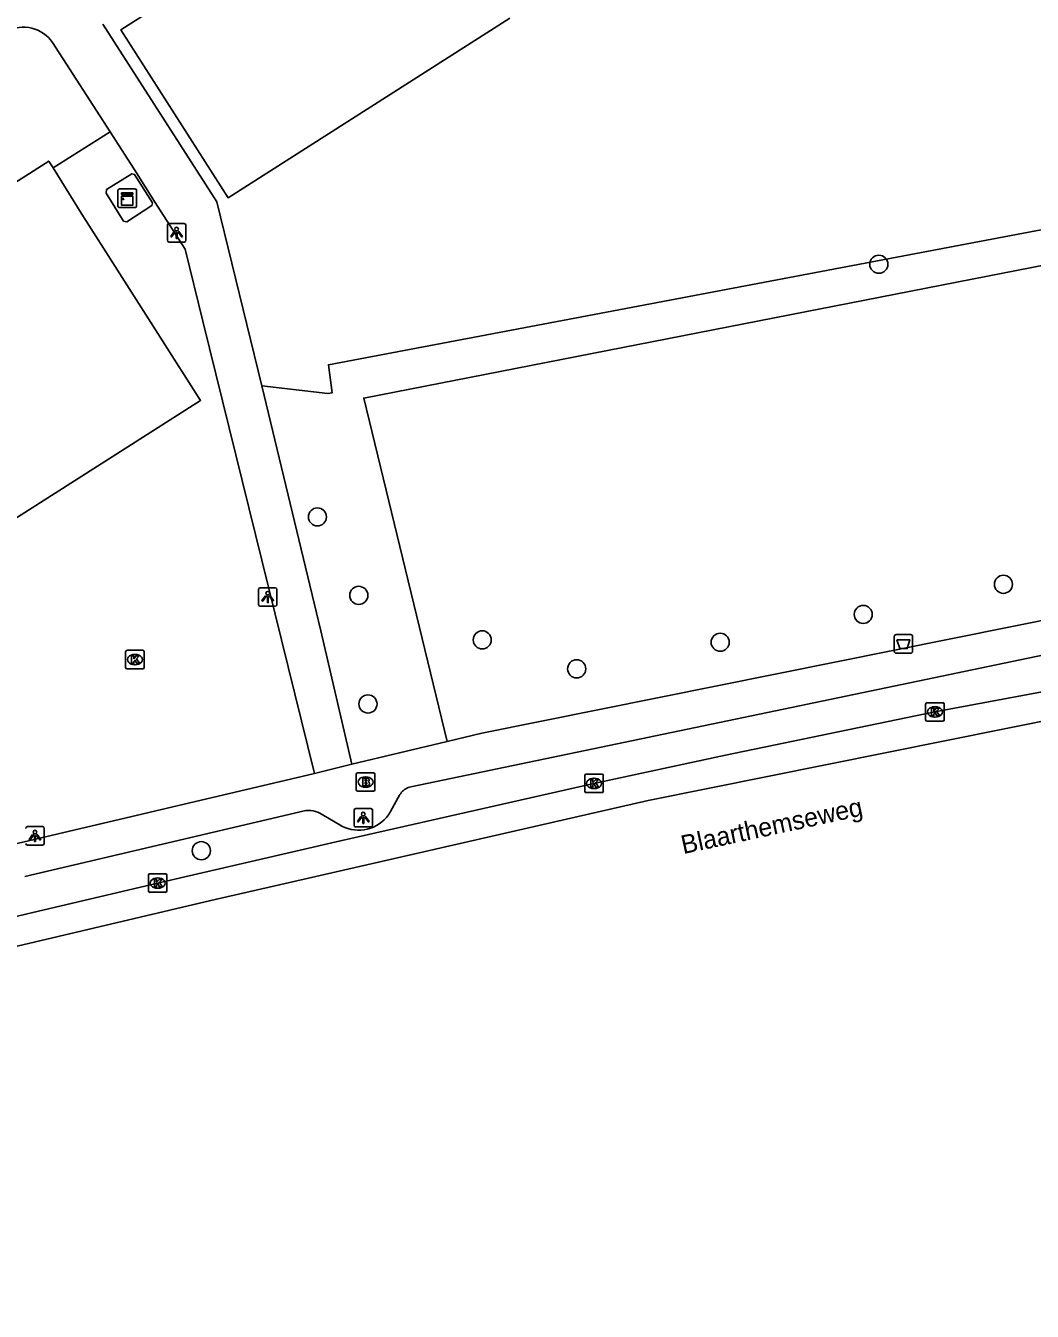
# Model space of a CAD drawing. Extents: x 159222 to 160346, y 381249 to 382166.
# Drawn here: x 159311.7 to 159366, y 381259.1 to 381328.4 of the extents above; entities that cross this region are included whole.
import ezdxf

# ---------------------------------------------------------------- set-up
doc = ezdxf.new("R2010")
doc.units = 0
for name, color, linetype in [('IMGEO_Afvalbak', 7, 'Continuous'), ('IMGEO_Boom', 7, 'Continuous'), ('IMGEO_Brandkraan', 7, 'Continuous'), ('IMGEO_Groenvoorziening', 7, 'Continuous'), ('IMGEO_Kast', 7, 'Continuous'), ('IMGEO_Kolk', 7, 'Continuous'), ('IMGEO_Lage_trafo', 7, 'Continuous'), ('IMGEO_Lichtpunt', 7, 'Continuous'), ('IMGEO_Openbare_ruimte_label', 7, 'Continuous'), ('IMGEO_Pand', 7, 'Continuous'), ('IMGEO_Rijbaan_lokaal_gesloten', 7, 'Continuous'), ('IMGEO_Voetpad_open', 7, 'Continuous')]:
    doc.layers.add(name, color=color, linetype=linetype)

msp = doc.modelspace()

# ---------------------------------------------------------------- linework, layer by layer
at = {"layer": 'IMGEO_Afvalbak'}
for p, q in [((159358.543, 381294.719), (159358.543, 381295.519)), ((159358.543, 381295.519), (159358.543, 381294.719)), ((159358.643, 381295.619), (159359.433, 381295.619)), ((159359.433, 381295.619), (159358.643, 381295.619)), ((159359.533, 381295.519), (159359.533, 381294.719)), ((159359.533, 381294.719), (159359.533, 381295.519)), ((159359.433, 381294.619), (159358.643, 381294.619)), ((159358.643, 381294.619), (159359.433, 381294.619))]:
    msp.add_line(p, q, dxfattribs=at)
msp.add_lwpolyline([(159358.686, 381295.333), (159359.39, 381295.333), (159359.241, 381294.863), (159358.835, 381294.863), (159358.686, 381295.333)], dxfattribs=at)
for centre, start, end in [((159358.643, 381295.519), 90, 180), ((159358.643, 381295.519), 90, 180), ((159359.433, 381295.519), 0, 90), ((159359.433, 381295.519), 360, 90), ((159358.643, 381294.719), 180, 270), ((159358.643, 381294.719), 180, 270), ((159359.433, 381294.719), 270, 0), ((159359.433, 381294.719), 270, 0)]:
    msp.add_arc(centre, 0.1, start, end, dxfattribs=at)
at = {"layer": 'IMGEO_Boom'}
for centre in [(159357.711, 381315.586), (159327.457, 381301.964), (159364.425, 381298.332), (159329.686, 381297.734), (159356.87, 381296.707), (159336.339, 381295.335), (159349.163, 381295.208), (159341.43, 381293.773), (159330.181, 381291.881), (159321.202, 381283.969)]:
    msp.add_circle(centre, 0.489, dxfattribs=at)
at = {"layer": 'IMGEO_Brandkraan'}
for p, q in [((159329.551, 381287.246), (159329.551, 381288.098)), ((159329.626, 381288.172), (159330.478, 381288.172)), ((159330.039, 381287.952), (159330.064, 381287.952)), ((159330.552, 381288.098), (159330.552, 381287.246)), ((159330.478, 381287.172), (159329.626, 381287.172)), ((159330.062, 381287.392), (159330.037, 381287.392))]:
    msp.add_line(p, q, dxfattribs=at)
for points in [[(159329.551, 381287.246), (159329.551, 381288.098)], [(159329.626, 381288.172), (159330.478, 381288.172)], [(159329.899, 381287.872), (159329.899, 381287.472), (159330.112, 381287.472)], [(159330.13, 381287.872), (159329.899, 381287.872)], [(159330.078, 381287.791), (159330.024, 381287.791), (159330.024, 381287.715)], [(159330.024, 381287.715), (159330.077, 381287.715)], [(159330.086, 381287.639), (159330.024, 381287.639), (159330.024, 381287.558)], [(159330.552, 381288.098), (159330.552, 381287.246)], [(159330.478, 381287.172), (159329.626, 381287.172)], [(159330.024, 381287.558), (159330.086, 381287.558)]]:
    msp.add_lwpolyline(points, dxfattribs=at)
for centre, radius, start, end in [((159329.628, 381288.096), 0.0765, 91.55205, 178.44795), ((159329.628, 381288.096), 0.0765, 91.55205, 178.44795), ((159330.079, 381287.753), 0.0379, 267.82845, 90.93552), ((159330.087, 381287.598), 0.0404, 269.87594, 90.50774), ((159330.134, 381287.727), 0.145, 59.4692, 91.53667), ((159330.159, 381287.774), 0.0922, 285.51372, 58.15012), ((159330.164, 381287.582), 0.105, 301.31148, 78.98903), ((159330.476, 381288.096), 0.0765, 1.55205, 88.44795), ((159330.476, 381288.096), 0.0765, 1.55205, 88.44795), ((159329.628, 381287.248), 0.0765, 181.55205, 268.44795), ((159329.628, 381287.248), 0.0765, 181.55205, 268.44795), ((159330.118, 381287.723), 0.251, 268.66757, 293.53466), ((159330.476, 381287.248), 0.0765, 271.55205, 358.44795), ((159330.476, 381287.248), 0.0765, 271.55205, 358.44795)]:
    msp.add_arc(centre, radius, start, end, dxfattribs=at)
for centre, major_axis, ratio, start_param, end_param in [((159330.038, 381287.672), (-0.387, 0.002), 0.722429, 4.712389, 7.853982), ((159330.063, 381287.672), (-0.39, 0.002), 0.717154, 1.570796, 4.712389)]:
    msp.add_ellipse(centre, major_axis=major_axis, ratio=ratio, start_param=start_param, end_param=end_param, dxfattribs=at)
at = {"layer": 'IMGEO_Groenvoorziening'}
for points in [[(159313.214, 381320.775), (159316.297, 381322.722)], [(159324.458, 381309.034), (159328.024, 381308.61), (159328.245, 381308.652), (159328.048, 381310.17), (159378.79, 381319.78), (159378.532, 381321.824), (159380.334, 381321.967), (159384.584, 381317.936), (159390.105, 381316.337)], [(159383.175, 381299.592), (159383.004, 381300.361), (159379.086, 381317.977), (159329.956, 381308.37), (159334.442, 381289.856)]]:
    msp.add_lwpolyline(points, dxfattribs=at)
at = {"layer": 'IMGEO_Kast'}
for p, q in [((159316.71, 381318.72), (159316.71, 381319.561)), ((159316.71, 381319.561), (159316.71, 381318.72)), ((159316.785, 381319.645), (159317.626, 381319.645)), ((159317.626, 381319.645), (159316.785, 381319.645)), ((159317.71, 381319.57), (159317.71, 381318.729)), ((159317.71, 381318.729), (159317.71, 381319.57)), ((159317.635, 381318.645), (159316.794, 381318.645)), ((159316.794, 381318.645), (159317.635, 381318.645))]:
    msp.add_line(p, q, dxfattribs=at)
for points in [[(159316.905, 381319.435), (159317.505, 381319.435), (159317.505, 381319.35), (159316.905, 381319.35), (159316.905, 381319.435)], [(159316.905, 381319.26), (159317.505, 381319.26), (159317.505, 381318.771), (159316.905, 381318.771), (159316.905, 381319.26)]]:
    msp.add_lwpolyline(points, dxfattribs=at)
msp.add_circle((159316.989, 381319.109), 0.0377, dxfattribs=at)
for centre, start, end in [((159316.788, 381319.567), 92.4484, 184.28452), ((159316.788, 381319.567), 92.4484, 184.28452), ((159317.632, 381319.567), 2.4484, 94.28452), ((159317.632, 381319.567), 2.4484, 94.28452), ((159316.788, 381318.723), 182.4484, 274.28452), ((159316.788, 381318.723), 182.4484, 274.28452), ((159317.632, 381318.723), 272.4484, 4.28452), ((159317.632, 381318.723), 272.4484, 4.28452)]:
    msp.add_arc(centre, 0.0779, start, end, dxfattribs=at)
at = {"layer": 'IMGEO_Kolk'}
for p, q in [((159317.122, 381293.846), (159317.122, 381294.698)), ((159317.197, 381294.772), (159318.049, 381294.772)), ((159317.61, 381294.552), (159317.635, 381294.552)), ((159318.123, 381294.698), (159318.123, 381293.846)), ((159317.633, 381293.992), (159317.608, 381293.992)), ((159318.049, 381293.772), (159317.197, 381293.772)), ((159360.233, 381291.024), (159360.233, 381291.876)), ((159360.308, 381291.95), (159361.16, 381291.95)), ((159360.721, 381291.73), (159360.746, 381291.73)), ((159361.234, 381291.876), (159361.234, 381291.024)), ((159360.744, 381291.17), (159360.719, 381291.17)), ((159361.16, 381290.95), (159360.308, 381290.95)), ((159341.863, 381287.172), (159341.863, 381288.024)), ((159341.938, 381288.098), (159342.79, 381288.098)), ((159342.351, 381287.878), (159342.376, 381287.878)), ((159342.864, 381288.024), (159342.864, 381287.172)), ((159342.79, 381287.098), (159341.938, 381287.098)), ((159342.374, 381287.318), (159342.349, 381287.318)), ((159318.424, 381282.725), (159319.276, 381282.725)), ((159318.349, 381281.799), (159318.349, 381282.651)), ((159318.837, 381282.505), (159318.862, 381282.505)), ((159319.35, 381282.651), (159319.35, 381281.799)), ((159319.276, 381281.725), (159318.424, 381281.725)), ((159318.86, 381281.945), (159318.835, 381281.945))]:
    msp.add_line(p, q, dxfattribs=at)
for points in [[(159317.122, 381293.846), (159317.122, 381294.698)], [(159317.197, 381294.772), (159318.049, 381294.772)], [(159318.123, 381294.698), (159318.123, 381293.846)], [(159317.443, 381294.472), (159317.566, 381294.472), (159317.566, 381294.321), (159317.696, 381294.472), (159317.86, 381294.472), (159317.714, 381294.321), (159317.867, 381294.072), (159317.715, 381294.072), (159317.63, 381294.236), (159317.566, 381294.169), (159317.566, 381294.072), (159317.443, 381294.072), (159317.443, 381294.472)], [(159318.049, 381293.772), (159317.197, 381293.772)], [(159360.233, 381291.024), (159360.233, 381291.876)], [(159360.308, 381291.95), (159361.16, 381291.95)], [(159361.234, 381291.876), (159361.234, 381291.024)], [(159360.554, 381291.65), (159360.677, 381291.65), (159360.677, 381291.499), (159360.807, 381291.65), (159360.971, 381291.65), (159360.825, 381291.499), (159360.978, 381291.25), (159360.826, 381291.25), (159360.741, 381291.414), (159360.677, 381291.347), (159360.677, 381291.25), (159360.554, 381291.25), (159360.554, 381291.65)], [(159361.16, 381290.95), (159360.308, 381290.95)], [(159341.863, 381287.172), (159341.863, 381288.024)], [(159341.938, 381288.098), (159342.79, 381288.098)], [(159342.184, 381287.798), (159342.307, 381287.798), (159342.307, 381287.647), (159342.437, 381287.798), (159342.601, 381287.798), (159342.455, 381287.647), (159342.608, 381287.398), (159342.456, 381287.398), (159342.371, 381287.562), (159342.307, 381287.495), (159342.307, 381287.398), (159342.184, 381287.398), (159342.184, 381287.798)], [(159342.864, 381288.024), (159342.864, 381287.172)], [(159342.79, 381287.098), (159341.938, 381287.098)], [(159318.424, 381282.725), (159319.276, 381282.725)], [(159318.349, 381281.799), (159318.349, 381282.651)], [(159318.67, 381282.425), (159318.793, 381282.425), (159318.793, 381282.274), (159318.923, 381282.425), (159319.087, 381282.425), (159318.941, 381282.274), (159319.094, 381282.025), (159318.942, 381282.025), (159318.857, 381282.189), (159318.793, 381282.122), (159318.793, 381282.025), (159318.67, 381282.025), (159318.67, 381282.425)], [(159319.35, 381282.651), (159319.35, 381281.799)], [(159319.276, 381281.725), (159318.424, 381281.725)]]:
    msp.add_lwpolyline(points, dxfattribs=at)
for centre, start, end in [((159317.199, 381294.696), 91.55205, 178.44795), ((159317.199, 381294.696), 91.55205, 178.44795), ((159318.047, 381294.696), 1.55205, 88.44795), ((159318.047, 381294.696), 1.55205, 88.44795), ((159317.199, 381293.848), 181.55205, 268.44795), ((159317.199, 381293.848), 181.55205, 268.44795), ((159318.047, 381293.848), 271.55205, 358.44795), ((159318.047, 381293.848), 271.55205, 358.44795), ((159360.31, 381291.874), 91.55205, 178.44795), ((159360.31, 381291.874), 91.55205, 178.44795), ((159361.158, 381291.874), 1.55205, 88.44795), ((159361.158, 381291.874), 1.55205, 88.44795), ((159360.31, 381291.026), 181.55205, 268.44795), ((159360.31, 381291.026), 181.55205, 268.44795), ((159361.158, 381291.026), 271.55205, 358.44795), ((159361.158, 381291.026), 271.55205, 358.44795), ((159341.94, 381288.022), 91.55205, 178.44795), ((159341.94, 381288.022), 91.55205, 178.44795), ((159342.788, 381288.022), 1.55205, 88.44795), ((159342.788, 381288.022), 1.55205, 88.44795), ((159341.94, 381287.174), 181.55205, 268.44795), ((159341.94, 381287.174), 181.55205, 268.44795), ((159342.788, 381287.174), 271.55205, 358.44795), ((159342.788, 381287.174), 271.55205, 358.44795), ((159318.426, 381282.649), 91.55205, 178.44795), ((159318.426, 381282.649), 91.55205, 178.44795), ((159319.274, 381282.649), 1.55205, 88.44795), ((159319.274, 381282.649), 1.55205, 88.44795), ((159318.426, 381281.801), 181.55205, 268.44795), ((159318.426, 381281.801), 181.55205, 268.44795), ((159319.274, 381281.801), 271.55205, 358.44795), ((159319.274, 381281.801), 271.55205, 358.44795)]:
    msp.add_arc(centre, 0.0765, start, end, dxfattribs=at)
for centre, major_axis, ratio, start_param, end_param in [((159317.609, 381294.272), (-0.387, 0.002), 0.722429, 4.712389, 7.853982), ((159317.634, 381294.272), (-0.39, 0.002), 0.717154, 1.570796, 4.712389), ((159360.72, 381291.45), (-0.387, 0.002), 0.722429, 4.712389, 7.853982), ((159360.745, 381291.45), (-0.39, 0.002), 0.717154, 1.570796, 4.712389), ((159342.35, 381287.598), (-0.387, 0.002), 0.722429, 4.712389, 7.853982), ((159342.375, 381287.598), (-0.39, 0.002), 0.717154, 1.570796, 4.712389), ((159318.836, 381282.225), (-0.387, 0.002), 0.722429, 4.712389, 7.853982), ((159318.861, 381282.225), (-0.39, 0.002), 0.717154, 1.570796, 4.712389)]:
    msp.add_ellipse(centre, major_axis=major_axis, ratio=ratio, start_param=start_param, end_param=end_param, dxfattribs=at)
at = {"layer": 'IMGEO_Lage_trafo'}
msp.add_lwpolyline([(159316.069, 381319.421), (159316.09, 381319.607), (159317.447, 381320.455), (159317.602, 381320.433), (159318.571, 381318.893), (159318.531, 381318.748), (159317.18, 381317.876), (159317.011, 381317.912), (159316.069, 381319.421)], dxfattribs=at)
at = {"layer": 'IMGEO_Lichtpunt'}
for p, q in [((159319.371, 381317.686), (159319.371, 381316.879)), ((159319.371, 381317.686), (159319.371, 381316.879)), ((159320.273, 381317.781), (159319.465, 381317.781)), ((159320.273, 381317.781), (159319.465, 381317.781)), ((159320.367, 381316.879), (159320.367, 381317.686)), ((159320.367, 381316.879), (159320.367, 381317.686)), ((159319.465, 381316.785), (159320.273, 381316.785)), ((159319.465, 381316.785), (159320.273, 381316.785)), ((159324.282, 381298.05), (159324.282, 381297.243)), ((159324.282, 381298.05), (159324.282, 381297.243)), ((159325.184, 381298.145), (159324.376, 381298.145)), ((159325.184, 381298.145), (159324.376, 381298.145)), ((159325.278, 381297.243), (159325.278, 381298.05)), ((159325.278, 381297.243), (159325.278, 381298.05)), ((159324.376, 381297.149), (159325.184, 381297.149)), ((159324.376, 381297.149), (159325.184, 381297.149)), ((159330.332, 381286.243), (159329.524, 381286.243)), ((159330.332, 381286.243), (159329.524, 381286.243)), ((159329.43, 381286.148), (159329.43, 381285.341)), ((159329.43, 381286.148), (159329.43, 381285.341)), ((159330.426, 381285.341), (159330.426, 381286.148)), ((159330.426, 381285.341), (159330.426, 381286.148)), ((159312.64, 381285.267), (159311.832, 381285.267)), ((159312.64, 381285.267), (159311.832, 381285.267)), ((159312.734, 381284.365), (159312.734, 381285.172)), ((159312.734, 381284.365), (159312.734, 381285.172)), ((159329.524, 381285.247), (159330.332, 381285.247)), ((159329.524, 381285.247), (159330.332, 381285.247)), ((159311.832, 381284.271), (159312.64, 381284.271)), ((159311.832, 381284.271), (159312.64, 381284.271))]:
    msp.add_line(p, q, dxfattribs=at)
for points in [[(159319.745, 381317.35), (159319.784, 381317.322), (159319.596, 381317.06), (159319.558, 381317.087), (159319.745, 381317.35)], [(159319.847, 381317.302), (159319.894, 381317.302), (159319.894, 381316.98), (159319.847, 381316.98), (159319.847, 381317.302)], [(159319.957, 381317.322), (159319.995, 381317.349), (159320.182, 381317.087), (159320.143, 381317.059), (159319.957, 381317.322)], [(159324.656, 381297.714), (159324.695, 381297.686), (159324.507, 381297.424), (159324.469, 381297.451), (159324.656, 381297.714)], [(159324.758, 381297.666), (159324.805, 381297.666), (159324.805, 381297.344), (159324.758, 381297.344), (159324.758, 381297.666)], [(159324.868, 381297.686), (159324.906, 381297.713), (159325.093, 381297.451), (159325.054, 381297.423), (159324.868, 381297.686)], [(159329.804, 381285.812), (159329.843, 381285.784), (159329.655, 381285.522), (159329.617, 381285.549), (159329.804, 381285.812)], [(159329.906, 381285.764), (159329.953, 381285.764), (159329.953, 381285.442), (159329.906, 381285.442), (159329.906, 381285.764)], [(159330.016, 381285.784), (159330.054, 381285.811), (159330.241, 381285.549), (159330.202, 381285.521), (159330.016, 381285.784)], [(159312.112, 381284.836), (159312.151, 381284.808), (159311.963, 381284.546), (159311.925, 381284.573), (159312.112, 381284.836)], [(159312.324, 381284.808), (159312.362, 381284.835), (159312.549, 381284.573), (159312.51, 381284.545), (159312.324, 381284.808)], [(159312.214, 381284.788), (159312.261, 381284.788), (159312.261, 381284.466), (159312.214, 381284.466), (159312.214, 381284.788)]]:
    msp.add_lwpolyline(points, dxfattribs=at)
for centre in [(159319.87, 381317.484), (159324.781, 381297.848), (159329.929, 381285.946), (159312.237, 381284.97)]:
    msp.add_circle(centre, 0.0994, dxfattribs=at)
for centre, start, end in [((159319.465, 381317.686), 90, 180), ((159319.465, 381317.686), 90, 180), ((159320.273, 381317.686), 0, 90), ((159320.273, 381317.686), 0, 90), ((159319.465, 381316.879), 180, 270), ((159319.465, 381316.879), 180, 270), ((159320.273, 381316.879), 270, 0), ((159320.273, 381316.879), 270, 360), ((159324.376, 381298.05), 90, 180), ((159324.376, 381298.05), 90, 180), ((159325.184, 381298.05), 0, 90), ((159325.184, 381298.05), 0, 90), ((159324.376, 381297.243), 180, 270), ((159324.376, 381297.243), 180, 270), ((159325.184, 381297.243), 270, 0), ((159325.184, 381297.243), 270, 360), ((159329.524, 381286.148), 90, 180), ((159329.524, 381286.148), 90, 180), ((159330.332, 381286.148), 0, 90), ((159330.332, 381286.148), 0, 90), ((159311.832, 381285.172), 90, 180), ((159311.832, 381285.172), 90, 180), ((159312.64, 381285.172), 0, 90), ((159312.64, 381285.172), 0, 90), ((159329.524, 381285.341), 180, 270), ((159329.524, 381285.341), 180, 270), ((159330.332, 381285.341), 270, 0), ((159330.332, 381285.341), 270, 360), ((159311.832, 381284.365), 180, 270), ((159311.832, 381284.365), 180, 270), ((159312.64, 381284.365), 270, 0), ((159312.64, 381284.365), 270, 360)]:
    msp.add_arc(centre, 0.0946, start, end, dxfattribs=at)
at = {"layer": 'IMGEO_Pand'}
for points in [[(159332.04, 381337.894), (159316.859, 381328.222), (159322.647, 381319.172), (159337.828, 381328.844)], [(159295.532, 381310.015), (159312.981, 381321.147), (159313.107, 381320.953), (159313.214, 381320.775)], [(159284.966, 381303.232), (159285.18, 381302.893), (159288.882, 381297.041), (159289.224, 381296.518), (159293.132, 381290.372), (159321.165, 381308.246), (159314.641, 381318.485), (159314.522, 381318.661), (159313.214, 381320.775)]]:
    msp.add_lwpolyline(points, dxfattribs=at)
at = {"layer": 'IMGEO_Rijbaan_lokaal_gesloten'}
for points in [[(159466.816, 381308.409), (159462.071, 381307.638), (159429.517, 381302.107), (159385.368, 381294.426), (159367.785, 381291.2), (159345.288, 381286.668), (159321.716, 381281.292), (159298.912, 381275.915), (159287.012, 381272.766), (159277.184, 381269.924), (159263.824, 381265.162), (159247.414, 381259.138)], [(159406.658, 381299.78), (159402.976, 381299.133), (159382.234, 381295.471), (159360.73, 381291.449), (159349.443, 381289.119), (159342.36, 381287.596), (159328.701, 381284.509), (159318.846, 381282.223), (159311.747, 381280.546), (159301.691, 381278.18), (159301.622, 381278.481)]]:
    msp.add_lwpolyline(points, dxfattribs=at)
at = {"layer": 'IMGEO_Voetpad_open'}
for points in [[(159324.458, 381309.034), (159322.032, 381318.947), (159315.892, 381328.525)], [(159310.53, 381328.046), (159310.572, 381328.073), (159310.722, 381328.158), (159310.879, 381328.229), (159311.042, 381328.286), (159311.21, 381328.329), (159311.38, 381328.356), (159311.553, 381328.367), (159311.725, 381328.364), (159311.897, 381328.345), (159312.066, 381328.31), (159312.232, 381328.261), (159312.392, 381328.197), (159312.547, 381328.119), (159312.693, 381328.027), (159312.831, 381327.923), (159312.959, 381327.807), (159313.076, 381327.68), (159313.181, 381327.543), (159316.297, 381322.722)], [(159316.297, 381322.722), (159317.711, 381320.508), (159318.674, 381318.976), (159320.33, 381316.403), (159321.286, 381312.523), (159327.292, 381288.14)], [(159329.32, 381288.63), (159327.648, 381295.817), (159324.458, 381309.034)], [(159383.175, 381299.592), (159377.496, 381298.59), (159336.317, 381290.305), (159334.442, 381289.856)], [(159311.692, 381282.577), (159326.837, 381286.14), (159326.969, 381286.143), (159327.098, 381286.133), (159327.225, 381286.113), (159327.351, 381286.081), (159327.472, 381286.038), (159327.59, 381285.984), (159328.626, 381285.379), (159328.778, 381285.292), (159328.938, 381285.218), (159329.104, 381285.159), (159329.274, 381285.115), (159329.447, 381285.087), (159329.623, 381285.074), (159329.798, 381285.077), (159329.973, 381285.095), (159330.146, 381285.129), (159330.314, 381285.178), (159330.478, 381285.243), (159330.635, 381285.321), (159330.785, 381285.413), (159330.925, 381285.519), (159331.056, 381285.636), (159331.176, 381285.765), (159331.284, 381285.903), (159331.379, 381286.051), (159331.399, 381286.087), (159331.889, 381286.964), (159331.905, 381286.993), (159331.944, 381287.057), (159331.989, 381287.116), (159332.039, 381287.172), (159332.094, 381287.223), (159332.153, 381287.268), (159332.216, 381287.309), (159332.282, 381287.343), (159332.352, 381287.371), (159332.423, 381287.393), (159332.496, 381287.409), (159374.721, 381296.22)], [(159334.442, 381289.856), (159329.32, 381288.63)], [(159327.292, 381288.14), (159329.32, 381288.63)], [(159327.292, 381288.14), (159300.508, 381281.819)]]:
    msp.add_lwpolyline(points, dxfattribs=at)

# ---------------------------------------------------------------- texts
at = {"layer": 'IMGEO_Openbare_ruimte_label'}
msp.add_text('Blaarthemseweg', height=1, rotation=12.11876, dxfattribs=at).set_placement((159347.171, 381283.784))

doc.saveas('drawing.dxf')
